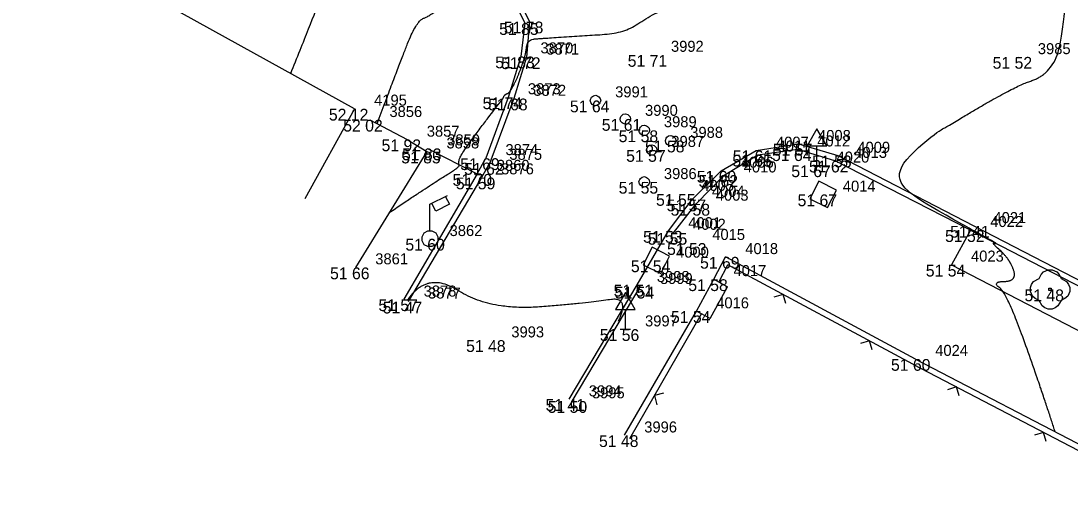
# Model space of a CAD drawing. Extents: x -704017 to -701500, y -1008977 to -1008450.
# Drawn here: x -701857.33 to -701830.65, y -1008916.6 to -1008904.58 of the extents above; entities that cross this region are included whole.
import ezdxf

# ---------------------------------------------------------------- set-up
doc = ezdxf.new("R2010")
doc.units = 0
for name, color, linetype in [('Z_body', 7, 'Continuous'), ('Z_body_cisla', 7, 'Continuous'), ('Z_body_vysky', 7, 'Continuous'), ('Z_budovy', 7, 'Continuous'), ('Z_chodnik', 7, 'Continuous'), ('Z_dopravni_znaceni', 7, 'Continuous'), ('Z_komunikace', 7, 'Continuous'), ('Z_obruby', 7, 'Continuous'), ('Z_oploceni', 7, 'Continuous'), ('Z_rozhrani_ploch', 7, 'Continuous'), ('Z_site_znaky_nerozlisene', 7, 'Continuous'), ('Z_site_znaky_pilire', 7, 'Continuous'), ('Z_site_znaky_VO', 7, 'Continuous'), ('Z_site_znaky_vodovod', 7, 'Continuous'), ('Z_vrstevnice_hlavni', 7, 'Continuous'), ('Z_vrstevnice_vedlejsi', 7, 'Continuous'), ('Z_zelen_jednotliva', 7, 'Continuous')]:
    doc.layers.add(name, color=color, linetype=linetype)

# ---------------------------------------------------------------- blocks, each defined once
blk = doc.blocks.new('POINT_DISPLAY')
blk.add_line((0, 0), (0, 0))
blk = doc.blocks.new('Z212')
for p, q in [((-0.17, 0.17), (0, 0)), ((0, 0), (0.17, 0.17))]:
    blk.add_line(p, q)
blk = doc.blocks.new('Z24')
for p, q in [((-0.42, 0.2), (-0.28, 0.28)), ((-0.28, 0.28), (-0.23, 0.38)), ((-0.23, 0.38), (-0.17, 0.45)), ((-0.17, 0.45), (-0.05, 0.5)), ((-0.05, 0.5), (0.05, 0.5)), ((0.05, 0.5), (0.17, 0.45)), ((0.17, 0.45), (0.23, 0.38)), ((0.23, 0.38), (0.28, 0.28)), ((0.28, 0.28), (0.42, 0.2)), ((-0.5, 0.05), (-0.47, 0.13)), ((-0.5, -0.05), (-0.5, 0.05)), ((-0.47, 0.13), (-0.42, 0.2)), ((-0.03, -0.03), (-0.03, 0.03)), ((-0.03, 0.03), (0.03, 0.03)), ((0.03, 0.03), (0.03, -0.03)), ((0.42, 0.2), (0.47, 0.13)), ((0.47, 0.13), (0.5, 0.05)), ((0.5, 0.05), (0.5, -0.05)), ((-0.45, -0.17), (-0.5, -0.05)), ((-0.38, -0.23), (-0.45, -0.17)), ((-0.28, -0.28), (-0.38, -0.23)), ((0.03, -0.03), (-0.03, -0.03)), ((0.38, -0.23), (0.28, -0.28)), ((0.45, -0.17), (0.38, -0.23)), ((0.5, -0.05), (0.45, -0.17)), ((-0.2, -0.42), (-0.28, -0.28)), ((-0.13, -0.47), (-0.2, -0.42)), ((-0.05, -0.5), (-0.13, -0.47)), ((0.05, -0.5), (-0.05, -0.5)), ((0.13, -0.47), (0.05, -0.5)), ((0.2, -0.42), (0.13, -0.47)), ((0.28, -0.28), (0.2, -0.42))]:
    blk.add_line(p, q)
blk = doc.blocks.new('Z13')
for p, q in [((0, 0.88), (0.45, 1.1)), ((0.4, 1.07), (0.5, 0.88)), ((0, 0.2), (0, 0.88)), ((0.15, 0.7), (0.05, 0.9)), ((0.5, 0.88), (0.15, 0.7)), ((-0.2, 0.05), (-0.15, 0.15)), ((-0.2, -0.05), (-0.2, 0.05)), ((-0.15, 0.15), (-0.05, 0.2)), ((-0.05, 0.2), (0.05, 0.2)), ((0.05, 0.2), (0.15, 0.15)), ((0.15, 0.15), (0.2, 0.05)), ((0.2, 0.05), (0.2, -0.05)), ((-0.15, -0.15), (-0.2, -0.05)), ((-0.05, -0.2), (-0.15, -0.15)), ((0.05, -0.2), (-0.05, -0.2)), ((0.15, -0.15), (0.05, -0.2)), ((0.2, -0.05), (0.15, -0.15))]:
    blk.add_line(p, q)
blk = doc.blocks.new('Z527')
for p, q in [((0, 0.93), (-0.25, 0.5)), ((0.25, 0.5), (0, 0.93)), ((-0.25, 0.5), (0.25, 0.5)), ((0, 0), (0, 0.5)), ((-0.13, 0), (0.13, 0))]:
    blk.add_line(p, q)
blk = doc.blocks.new('Z608')
for p, q in [((0.25, 0.25), (-0.25, 0.25)), ((-0.25, 0.25), (-0.25, -0.25)), ((0.25, -0.25), (0.25, 0.25)), ((-0.25, -0.25), (0.25, -0.25))]:
    blk.add_line(p, q)
blk = doc.blocks.new('Z614')
for p, q in [((-0.13, 0.03), (-0.1, 0.08)), ((-0.13, -0.03), (-0.13, 0.03)), ((-0.1, 0.08), (-0.08, 0.1)), ((-0.08, 0.1), (-0.03, 0.13)), ((-0.03, 0.13), (0.03, 0.13)), ((0.03, 0.13), (0.08, 0.1)), ((0.08, 0.1), (0.1, 0.08)), ((0.1, 0.08), (0.13, 0.03)), ((0.13, 0.03), (0.13, -0.03)), ((-0.1, -0.08), (-0.13, -0.03)), ((-0.08, -0.1), (-0.1, -0.08)), ((-0.03, -0.13), (-0.08, -0.1)), ((0.03, -0.13), (-0.03, -0.13)), ((0.08, -0.1), (0.03, -0.13)), ((0.1, -0.08), (0.08, -0.1)), ((0.13, -0.03), (0.1, -0.08))]:
    blk.add_line(p, q)

msp = doc.modelspace()

# ---------------------------------------------------------------- linework, layer by layer
at = {"layer": 'Z_budovy'}
for q in [(-701857.33, -1008902.12), (-701850.11, -1008909.11)]:
    msp.add_line((-701848.85, -1008906.82), q, dxfattribs=at)
at = {"layer": 'Z_chodnik'}
for p, q in [((-701833.18, -1008909.91), (-701833.67, -1008910.79)), ((-701833.67, -1008910.79), (-701821.14, -1008917.29))]:
    msp.add_line(p, q, dxfattribs=at)
at = {"layer": 'Z_komunikace'}
for p, q in [((-701844.72, -1008903.97), (-701844.4, -1008904.6)), ((-701844.4, -1008904.6), (-701844.47, -1008905.51)), ((-701844.47, -1008905.51), (-701844.8, -1008906.56)), ((-701844.8, -1008906.56), (-701845.41, -1008908.2)), ((-701838.63, -1008907.88), (-701837.56, -1008907.71)), ((-701837.56, -1008907.71), (-701836.56, -1008908.01)), ((-701839.52, -1008908.4), (-701838.63, -1008907.88)), ((-701836.56, -1008908.01), (-701833.1, -1008909.8)), ((-701845.41, -1008908.2), (-701845.62, -1008908.57)), ((-701845.62, -1008908.57), (-701847.48, -1008911.73)), ((-701840.26, -1008909.13), (-701839.52, -1008908.4)), ((-701840.86, -1008909.93), (-701840.26, -1008909.13)), ((-701841.66, -1008911.3), (-701840.86, -1008909.93)), ((-701833.1, -1008909.8), (-701820.65, -1008916.24)), ((-701843.39, -1008914.21), (-701841.66, -1008911.3))]:
    msp.add_line(p, q, dxfattribs=at)
at = {"layer": 'Z_obruby'}
for p, q in [((-701844.8, -1008904.06), (-701844.52, -1008904.64)), ((-701844.52, -1008904.64), (-701844.62, -1008905.49)), ((-701844.62, -1008905.49), (-701844.94, -1008906.53)), ((-701844.94, -1008906.53), (-701845.51, -1008908.08)), ((-701838.59, -1008907.99), (-701837.58, -1008907.85)), ((-701837.58, -1008907.85), (-701836.64, -1008908.14)), ((-701845.73, -1008908.48), (-701845.51, -1008908.08)), ((-701839.45, -1008908.51), (-701838.59, -1008907.99)), ((-701833.18, -1008909.91), (-701836.64, -1008908.14)), ((-701845.73, -1008908.48), (-701847.59, -1008911.67)), ((-701840.16, -1008909.24), (-701839.45, -1008908.51)), ((-701840.74, -1008909.98), (-701840.16, -1008909.24)), ((-701840.74, -1008909.98), (-701840.86, -1008909.93)), ((-701833.18, -1008909.91), (-701820.69, -1008916.37)), ((-701841.58, -1008911.35), (-701841.66, -1008911.3)), ((-701843.31, -1008914.26), (-701841.58, -1008911.35))]:
    msp.add_line(p, q, dxfattribs=at)
at = {"layer": 'Z_oploceni'}
for p, q in [((-701847.51, -1008907.6), (-701847.01, -1008907.91)), ((-701847.01, -1008907.91), (-701848.82, -1008910.86)), ((-701839.71, -1008911.16), (-701839.41, -1008910.59)), ((-701834.58, -1008913.19), (-701839.41, -1008910.59)), ((-701839.58, -1008911.23), (-701839.35, -1008910.79)), ((-701834.65, -1008913.32), (-701839.35, -1008910.79)), ((-701841.98, -1008915.13), (-701840.15, -1008911.97)), ((-701841.85, -1008915.21), (-701840.02, -1008912.04)), ((-701834.65, -1008913.32), (-701822.23, -1008919.8)), ((-701834.58, -1008913.19), (-701822.16, -1008919.67))]:
    msp.add_line(p, q, dxfattribs=at)
at = {"layer": 'Z_rozhrani_ploch'}
msp.add_line((-701846.99, -1008907.83), (-701845.73, -1008908.48), dxfattribs=at)
at = {"layer": 'Z_site_znaky_pilire'}
for p, q in [((-701848.46, -1008907.1), (-701847.51, -1008907.6)), ((-701840.15, -1008911.97), (-701839.71, -1008911.16)), ((-701839.71, -1008911.16), (-701839.36, -1008911.35)), ((-701839.8, -1008912.16), (-701839.36, -1008911.35)), ((-701839.8, -1008912.16), (-701840.15, -1008911.97))]:
    msp.add_line(p, q, dxfattribs=at)
at = {"layer": 'Z_vrstevnice_hlavni'}
msp.add_open_spline([(-701848.27, -1008907.2), (-701847.745, -1008905.785), (-701847.265, -1008904.572), (-701846.905, -1008904.456), (-701845.948, -1008903.618), (-701845.701, -1008903.396), (-701845.878, -1008903.285), (-701846.797, -1008902.675), (-701846.819, -1008902.461), (-701844.274, -1008900.657), (-701843.315, -1008899.847), (-701843.128, -1008899.489), (-701841.298, -1008896.479), (-701840.936, -1008896.63), (-701839.794, -1008897.089), (-701839.943, -1008896.926), (-701837.967, -1008896.305), (-701837.352, -1008895.94), (-701837.297, -1008895.909), (-701837.249, -1008895.914), (-701837.651, -1008895.668), (-701838.408, -1008895.19), (-701838.46, -1008895.152), (-701838.456, -1008895.059), (-701837.745, -1008894.493), (-701837.353, -1008894.158)], degree=2, dxfattribs=at)
at = {"layer": 'Z_vrstevnice_vedlejsi'}
for points in [[(-701850.471, -1008905.921), (-701849.492, -1008903.516), (-701849.364, -1008902.78), (-701849.098, -1008901.832), (-701848.969, -1008901.714), (-701849.218, -1008901.558), (-701850.524, -1008900.762), (-701850.642, -1008900.68), (-701849.911, -1008899.861), (-701847.462, -1008897.791), (-701846.495, -1008895.943), (-701845.512, -1008894.327), (-701844.545, -1008894.73), (-701843.842, -1008895.012), (-701844.524, -1008894.269), (-701843.583, -1008893.973), (-701841.535, -1008893.753), (-701842.348, -1008893.24), (-701842.66, -1008893.013), (-701842.656, -1008892.93)], [(-701847.963, -1008909.463), (-701846.978, -1008908.798), (-701846.157, -1008908.29), (-701846.215, -1008908.23), (-701846.144, -1008907.973), (-701845.168, -1008906.674), (-701845.083, -1008906.589), (-701845.029, -1008906.455), (-701844.904, -1008906.414), (-701844.716, -1008906.061), (-701844.511, -1008905.505), (-701844.482, -1008905.309), (-701844.435, -1008905.055), (-701844.056, -1008905.027), (-701842.946, -1008904.954), (-701841.951, -1008904.886), (-701841.243, -1008904.375), (-701839.666, -1008903.774), (-701837.742, -1008900.901), (-701836.724, -1008898.953), (-701836.663, -1008898.845), (-701836.388, -1008898.915), (-701835.582, -1008899.242), (-701834.737, -1008898.317), (-701834.19, -1008897.48)], [(-701831.031, -1008915.041), (-701831.302, -1008914.19), (-701832.238, -1008911.533), (-701832.65, -1008911.22), (-701831.997, -1008911.21), (-701832.17, -1008910.665), (-701832.668, -1008910.209), (-701832.486, -1008910.269), (-701832.635, -1008910.185), (-701833.165, -1008909.89), (-701835.695, -1008908.458), (-701832.175, -1008906.282), (-701831.142, -1008905.952), (-701830.791, -1008904.875), (-701830.674, -1008901.918), (-701828.027, -1008903.192), (-701826.636, -1008903.859), (-701826.177, -1008903.735), (-701825.973, -1008903.713), (-701825.021, -1008903.149)], [(-701842.137, -1008912.23), (-701841.833, -1008911.591), (-701842.893, -1008911.77), (-701845.407, -1008911.957), (-701847.015, -1008910.94), (-701847.513, -1008911.712)]]:
    msp.add_open_spline(points, degree=2, dxfattribs=at)

# ---------------------------------------------------------------- block references
at = {"layer": 'Z_body'}
for p in [(-701844.52, -1008904.64), (-701844.4, -1008904.6), (-701841.3, -1008905.45), (-701844.62, -1008905.49), (-701844.47, -1008905.51), (-701831.97, -1008905.5), (-701844.94, -1008906.53), (-701844.8, -1008906.56), (-701842.72, -1008906.61), (-701848.85, -1008906.82), (-701848.46, -1008907.1), (-701841.96, -1008907.08), (-701841.48, -1008907.37), (-701847.51, -1008907.6), (-701846.99, -1008907.83), (-701840.81, -1008907.63), (-701837.58, -1008907.85), (-701837.56, -1008907.71), (-701847.01, -1008907.91), (-701845.51, -1008908.08), (-701841.29, -1008907.87), (-701838.63, -1008907.88), (-701838.59, -1008907.99), (-701836.56, -1008908.01), (-701845.41, -1008908.2), (-701837.09, -1008908.26), (-701836.64, -1008908.14), (-701845.73, -1008908.48), (-701845.62, -1008908.57), (-701839.52, -1008908.4), (-701839.45, -1008908.51), (-701841.48, -1008908.68), (-701840.53, -1008908.99), (-701840.26, -1008909.13), (-701836.93, -1008909), (-701840.16, -1008909.24), (-701840.86, -1008909.93), (-701840.74, -1008909.98), (-701833.18, -1008909.91), (-701833.1, -1008909.8), (-701846.93, -1008910.13), (-701840.25, -1008910.24), (-701841.17, -1008910.68), (-701839.41, -1008910.59), (-701848.82, -1008910.86), (-701833.67, -1008910.79), (-701841.66, -1008911.3), (-701839.71, -1008911.16), (-701841.58, -1008911.35), (-701831.16, -1008911.42), (-701847.59, -1008911.67), (-701847.48, -1008911.73), (-701840.15, -1008911.97), (-701841.96, -1008912.43), (-701845.36, -1008912.71), (-701834.58, -1008913.19), (-701843.39, -1008914.21), (-701843.31, -1008914.26), (-701841.98, -1008915.13)]:
    msp.add_blockref('POINT_DISPLAY', p, dxfattribs=at)
at = {"layer": 'Z_dopravni_znaceni'}
for p in [(-701837.09, -1008908.26), (-701841.96, -1008912.43)]:
    msp.add_blockref('Z527', p, dxfattribs=at)
at = {"layer": 'Z_oploceni'}
for p, rotation in [((-701837.95, -1008911.55), 151.7), ((-701835.75, -1008912.73), 151.7), ((-701841.22, -1008914.12), -120.10000000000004), ((-701833.54, -1008913.9), 152.4), ((-701831.33, -1008915.06), 152.4)]:
    msp.add_blockref('Z212', p, dxfattribs=dict(at, rotation=rotation))
at = {"layer": 'Z_site_znaky_nerozlisene', "rotation": -27.000000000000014}
for p in [(-701836.93, -1008909), (-701841.17, -1008910.68)]:
    msp.add_blockref('Z608', p, dxfattribs=at)
at = {"layer": 'Z_site_znaky_VO'}
msp.add_blockref('Z13', (-701846.93, -1008910.13), dxfattribs=at)
at = {"layer": 'Z_site_znaky_vodovod', "rotation": 10.799999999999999}
for p in [(-701842.72, -1008906.61), (-701841.96, -1008907.08), (-701841.48, -1008907.37), (-701840.81, -1008907.63), (-701841.29, -1008907.87), (-701841.48, -1008908.68)]:
    msp.add_blockref('Z614', p, dxfattribs=at)
at = {"layer": 'Z_zelen_jednotliva'}
msp.add_blockref('Z24', (-701831.16, -1008911.42), dxfattribs=at)

# ---------------------------------------------------------------- texts
at = {"layer": 'Z_body_cisla'}
for s, p in [('3870', (-701844.12, -1008905.41)), ('3871', (-701843.97, -1008905.44)), ('3992', (-701840.8, -1008905.37)), ('3985', (-701831.47, -1008905.43)), ('3873', (-701844.44, -1008906.45)), ('3872', (-701844.3, -1008906.49)), ('3991', (-701842.22, -1008906.53)), ('4195', (-701848.35, -1008906.74)), ('3856', (-701847.96, -1008907.03)), ('3990', (-701841.46, -1008907)), ('3989', (-701840.98, -1008907.29)), ('3857', (-701847.01, -1008907.53)), ('3988', (-701840.31, -1008907.56)), ('3858', (-701846.51, -1008907.83)), ('3859', (-701846.49, -1008907.75)), ('3987', (-701840.79, -1008907.79)), ('4007', (-701838.13, -1008907.81)), ('4012', (-701837.08, -1008907.78)), ('4008', (-701837.06, -1008907.64)), ('3874', (-701845.01, -1008908)), ('3875', (-701844.91, -1008908.12)), ('4011', (-701838.09, -1008907.91)), ('4013', (-701836.14, -1008908.07)), ('4009', (-701836.06, -1008907.94)), ('3860', (-701845.23, -1008908.4)), ('4006', (-701839.02, -1008908.32)), ('4020', (-701836.59, -1008908.19)), ('3876', (-701845.12, -1008908.49)), ('3986', (-701840.98, -1008908.61)), ('4010', (-701838.95, -1008908.44)), ('4005', (-701840.03, -1008908.91)), ('4014', (-701836.43, -1008908.93)), ('4004', (-701839.76, -1008909.06)), ('4003', (-701839.66, -1008909.16)), ('4021', (-701832.6, -1008909.73)), ('4001', (-701840.36, -1008909.86)), ('4002', (-701840.24, -1008909.9)), ('4022', (-701832.68, -1008909.83)), ('3862', (-701846.43, -1008910.06)), ('4015', (-701839.75, -1008910.16)), ('4018', (-701838.91, -1008910.52)), ('3861', (-701848.32, -1008910.78)), ('4000', (-701840.67, -1008910.61)), ('4023', (-701833.17, -1008910.71)), ('3998', (-701841.16, -1008911.23)), ('3999', (-701841.08, -1008911.28)), ('4017', (-701839.21, -1008911.08)), ('3878', (-701847.09, -1008911.6)), ('3877', (-701846.98, -1008911.65)), ('4016', (-701839.65, -1008911.9)), ('3997', (-701841.46, -1008912.36)), ('3993', (-701844.86, -1008912.64)), ('4024', (-701834.08, -1008913.11)), ('3994', (-701842.89, -1008914.14)), ('3995', (-701842.81, -1008914.19)), ('3996', (-701841.48, -1008915.06))]:
    msp.add_text(s, height=0.28, dxfattribs=at).set_placement(p)
at = {"layer": 'Z_body_vysky'}
for s, p in [('51 85', (-701845.17, -1008904.94)), ('51 78', (-701845.05, -1008904.9)), ('51 71', (-701841.9, -1008905.75)), ('51 83', (-701845.27, -1008905.79)), ('51 72', (-701845.12, -1008905.81)), ('51 52', (-701832.62, -1008905.8)), ('51 74', (-701845.59, -1008906.83)), ('51 68', (-701845.45, -1008906.86)), ('51 64', (-701843.37, -1008906.91)), ('52 12', (-701849.5, -1008907.12)), ('52 02', (-701849.135, -1008907.4)), ('51 61', (-701842.56, -1008907.38)), ('51 58', (-701842.13, -1008907.67)), ('51 92', (-701848.16, -1008907.9)), ('51 83', (-701847.64, -1008908.13)), ('51 58', (-701841.46, -1008907.93)), ('51 64', (-701838.23, -1008908.15)), ('51 57', (-701838.21, -1008908.01)), ('51 85', (-701847.66, -1008908.21)), ('51 69', (-701846.16, -1008908.38)), ('51 57', (-701841.94, -1008908.17)), ('51 65', (-701839.24, -1008908.29)), ('51 61', (-701839.23, -1008908.18)), ('51 53', (-701837.21, -1008908.31)), ('51 62', (-701846.06, -1008908.5)), ('51 67', (-701837.74, -1008908.56)), ('51 62', (-701837.29, -1008908.44)), ('51 70', (-701846.355, -1008908.78)), ('51 59', (-701846.27, -1008908.87)), ('51 60', (-701840.145, -1008908.7)), ('51 62', (-701840.1, -1008908.81)), ('51 55', (-701842.13, -1008908.98)), ('51 55', (-701841.18, -1008909.29)), ('51 57', (-701840.91, -1008909.43)), ('51 67', (-701837.58, -1008909.3)), ('51 58', (-701840.81, -1008909.54)), ('51 53', (-701841.51, -1008910.23)), ('51 55', (-701841.39, -1008910.28)), ('51 52', (-701833.83, -1008910.21)), ('51 41', (-701833.7, -1008910.1)), ('51 60', (-701847.555, -1008910.43)), ('51 53', (-701840.9, -1008910.54)), ('51 54', (-701841.82, -1008910.98)), ('51 69', (-701840.06, -1008910.89)), ('51 66', (-701849.47, -1008911.16)), ('51 54', (-701834.32, -1008911.09)), ('51 51', (-701842.26, -1008911.6)), ('51 58', (-701840.36, -1008911.46)), ('51 54', (-701842.23, -1008911.65)), ('51 48', (-701831.81, -1008911.72)), ('51 57', (-701848.24, -1008911.97)), ('51 47', (-701848.13, -1008912.03)), ('51 54', (-701840.8, -1008912.27)), ('51 56', (-701842.61, -1008912.73)), ('51 48', (-701846.01, -1008913.01)), ('51 60', (-701835.205, -1008913.49)), ('51 41', (-701843.99, -1008914.51)), ('51 50', (-701843.935, -1008914.56)), ('51 48', (-701842.63, -1008915.43))]:
    msp.add_text(s, height=0.3, dxfattribs=at).set_placement(p)

doc.saveas('drawing.dxf')
